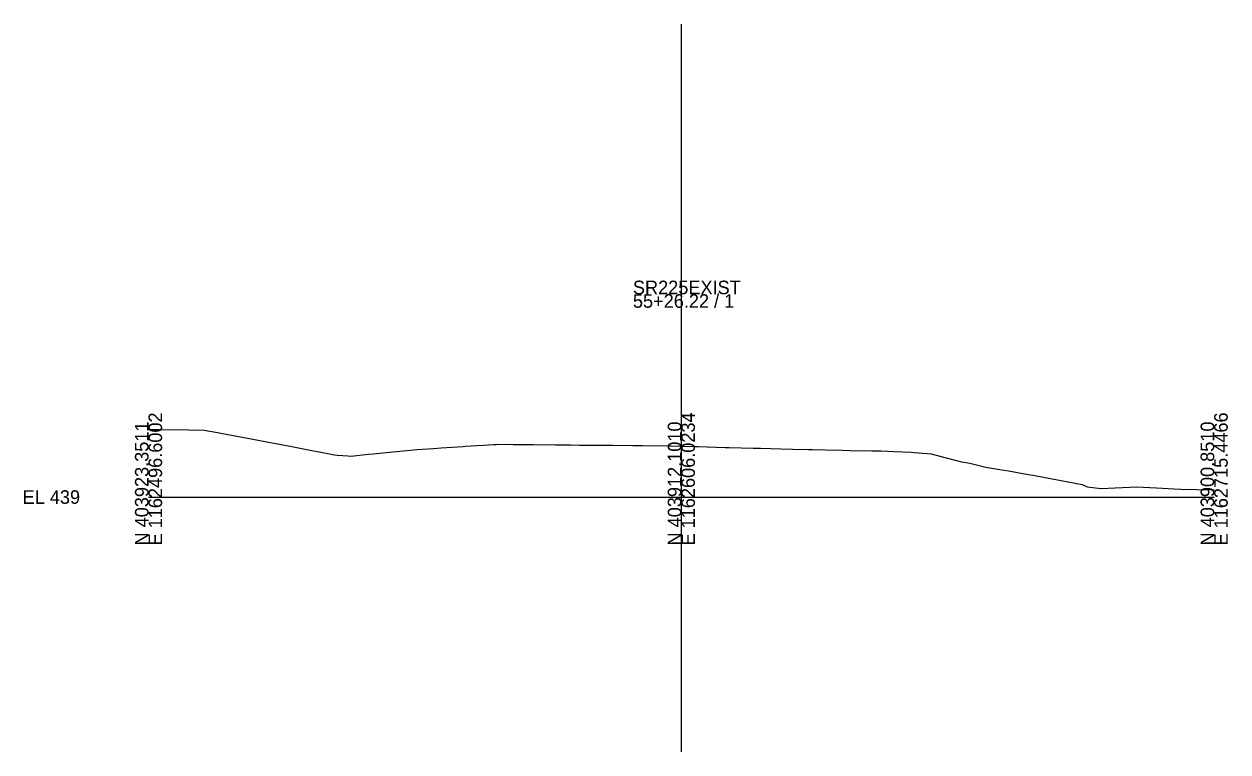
# Model space of a CAD drawing. Extents: x -26 to 246, y -78 to 2098.
# Drawn here: x -25.7 to 222.8, y 1947.4 to 2097.7 of the extents above; entities that cross this region are included whole.
import ezdxf

# ---------------------------------------------------------------- set-up
doc = ezdxf.new("R2010")
doc.units = 0
for name, color, linetype in [('DESIGN - SCRATCH - User 2', 7, 'Continuous'), ('DESIGN - SHEET - Light Grid', 7, 'Continuous'), ('SURVEY - GROUND - Top of Ground', 7, 'Continuous')]:
    doc.layers.add(name, color=color, linetype=linetype)

msp = doc.modelspace()

# ---------------------------------------------------------------- linework, layer by layer
at = {"layer": 'DESIGN - SCRATCH - User 2'}
msp.add_line((110, 1947.35), (110, 2097.7), dxfattribs=at)
at = {"layer": 'DESIGN - SHEET - Light Grid'}
for p, q in [((110, 2000), (110, 2041.9)), ((0, 2000), (110, 2000)), ((110, 2000), (220, 2000))]:
    msp.add_line(p, q, dxfattribs=at)
at = {"layer": 'SURVEY - GROUND - Top of Ground'}
msp.add_lwpolyline([(0, 2013.97), (2.26, 2013.94), (8.33, 2013.87), (11.48, 2013.84), (14.27, 2013.31), (14.92, 2013.19), (19.35, 2012.36), (21.17, 2012.01), (24.44, 2011.4), (27.39, 2010.83), (29.58, 2010.42), (34.03, 2009.56), (34.85, 2009.39), (38.36, 2008.72), (38.95, 2008.67), (40.09, 2008.58), (41.16, 2008.49), (41.74, 2008.45), (45.43, 2008.86), (46.38, 2008.93), (50.42, 2009.35), (52.61, 2009.52), (55.42, 2009.79), (58.8, 2010.03), (60.44, 2010.18), (64.97, 2010.47), (65.47, 2010.52), (67.76, 2010.65), (69.17, 2010.73), (71.21, 2010.86), (71.74, 2010.89), (72.09, 2010.91), (75.25, 2010.89), (78.07, 2010.87), (79.45, 2010.85), (84.01, 2010.79), (85.05, 2010.78), (87.1, 2010.76), (88.98, 2010.74), (92.15, 2010.72), (95.15, 2010.69), (95.76, 2010.69), (99.97, 2010.64), (101.55, 2010.64), (101.98, 2010.63), (107.12, 2010.57), (107.87, 2010.57), (110.05, 2010.54), (112.54, 2010.47), (113.44, 2010.44), (119.05, 2010.27), (119.85, 2010.25), (124.86, 2010.11), (126.33, 2010.08), (130.6, 2009.96), (132.93, 2009.92), (136.24, 2009.83), (137.1, 2009.82), (139.69, 2009.75), (143.17, 2009.68), (144.78, 2009.64), (149.31, 2009.55), (149.72, 2009.54), (151.17, 2009.52), (153.92, 2009.39), (157.43, 2009.25), (158.06, 2009.23), (159.02, 2009.14), (161.59, 2008.9), (163.33, 2008.45), (167.85, 2007.3), (169.56, 2006.98), (172.89, 2006.18), (175.74, 2005.67), (177.52, 2005.39), (181.28, 2004.7), (182.98, 2004.43), (187.68, 2003.56), (188.44, 2003.43), (192.74, 2002.62), (193.78, 2002.13), (196.69, 2001.77), (203.96, 2002.08), (208.07, 2001.88), (211.71, 2001.71), (213.15, 2001.64), (216.44, 2001.56), (219.47, 2001.48), (220, 2001.47)], dxfattribs=at)

# ---------------------------------------------------------------- texts
at = {"layer": 'DESIGN - SHEET - Light Grid'}
for s, p in [('SR225EXIST', (100, 2041.9)), ('55+26.22 / 1', (100, 2039.1)), ('EL 439', (-26, 1998.6))]:
    msp.add_text(s, height=2.8, dxfattribs=at).set_placement(p)
for s, p in [('E 1162496.6002', (2.8, 1990)), ('E 1162606.0234', (112.8, 1990)), ('E 1162715.4466', (222.8, 1990)), ('N 403923.3511', (0, 1990)), ('N 403912.1010', (110, 1990)), ('N 403900.8510', (220, 1990))]:
    msp.add_text(s, height=2.8, rotation=90, dxfattribs=at).set_placement(p)

doc.saveas('drawing.dxf')
